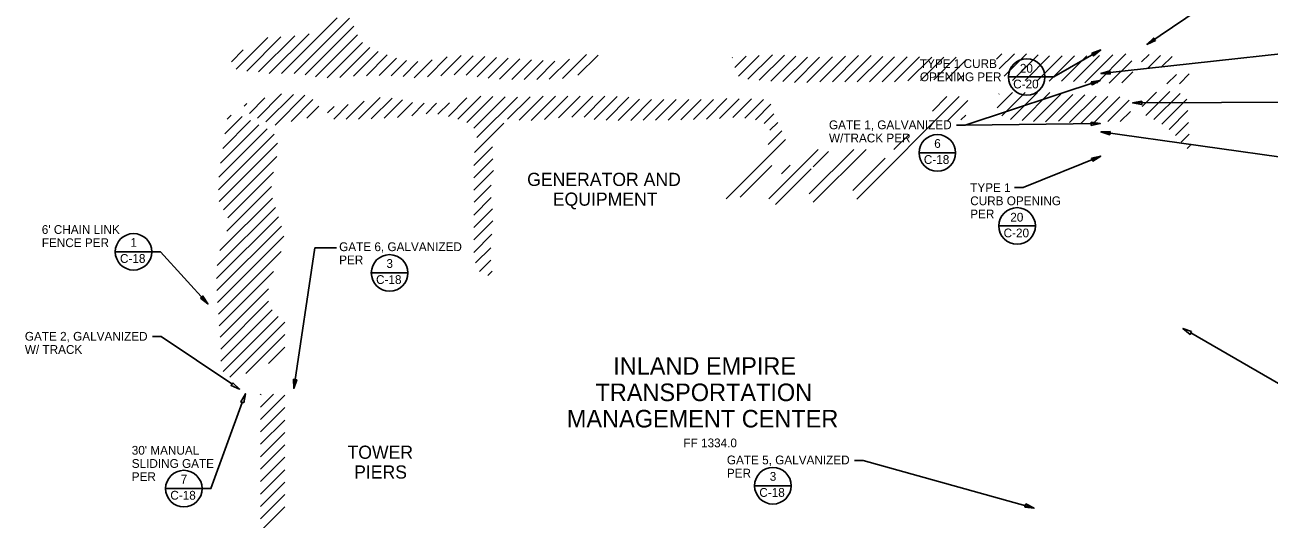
# Model space of a CAD drawing. Extents: x 0 to 3.5, y 0 to 2.5.
# Drawn here: x 0.832 to 2.248, y 0.842 to 1.404 of the extents above; entities that cross this region are included whole.
import ezdxf

# ---------------------------------------------------------------- set-up
doc = ezdxf.new("R2010")
doc.units = 0
for name, color, linetype in [('C-MARK', 7, 'Continuous'), ('C-TEXT', 7, 'Continuous'), ('C-TEXT-TITL', 7, 'Continuous'), ('G-TEXT', 7, 'Continuous'), ('Pavement Hatch', 7, 'Continuous')]:
    doc.layers.add(name, color=color, linetype=linetype)

msp = doc.modelspace()

# ---------------------------------------------------------------- linework, layer by layer
at = {"layer": 'C-MARK'}
for p, q in [((1.9515, 1.345), (1.9931, 1.345)), ((1.8498, 1.2586), (1.8914, 1.2586)), ((1.9406, 1.1754), (1.9822, 1.1754)), ((0.9347, 1.1459), (0.9764, 1.1459)), ((1.2262, 1.1219), (1.2678, 1.1219)), ((1.6625, 0.8795), (1.7042, 0.8795)), ((0.9919, 0.8763), (1.0336, 0.8763))]:
    msp.add_line(p, q, dxfattribs=at)
for points in [[(2.3985, 1.5709), (2.3885, 1.5709), (2.1092, 1.3821)], [(1.9931, 1.345), (2.0031, 1.345), (2.0566, 1.3758)], [(2.4063, 1.386), (2.3963, 1.386), (2.0568, 1.3491)], [(1.8922, 1.2901), (1.9022, 1.2901), (2.0561, 1.3411)], [(2.4072, 1.3169), (2.3972, 1.3169), (2.0929, 1.3154)], [(1.8922, 1.2901), (1.9022, 1.2901), (2.0561, 1.2919)], [(2.4072, 1.2349), (2.3972, 1.2349), (2.0568, 1.2825)], [(1.9583, 1.219), (1.9683, 1.219), (2.0566, 1.255)], [(1.1866, 1.1503), (1.162, 1.1503), (1.138, 0.9903)], [(0.9764, 1.1459), (0.9864, 1.1459), (1.0403, 1.0866)], [(0.9771, 1.0493), (0.9871, 1.0493), (1.0676, 0.9954)], [(2.3274, 0.9621), (2.3174, 0.9621), (2.1591, 1.0535)], [(1.0336, 0.8763), (1.0436, 0.8763), (1.0793, 0.9744)], [(1.7763, 0.9082), (1.7863, 0.9082), (1.9807, 0.854)]]:
    msp.add_lwpolyline(points, dxfattribs=at)
for centre in [(1.9723, 1.345), (1.8706, 1.2586), (1.9614, 1.1754), (0.9555, 1.1459), (1.247, 1.1219), (1.0128, 0.8763), (1.6833, 0.8795)]:
    msp.add_circle(centre, 0.0208, dxfattribs=at)
at = {"layer": 'C-TEXT'}
for points in [[(2.1189, 1.3864), (2.1092, 1.3821), (2.1168, 1.3894)], [(2.0466, 1.3722), (2.0566, 1.3758), (2.0484, 1.369)], [(2.0669, 1.352), (2.0568, 1.3491), (2.0673, 1.3484)], [(2.0456, 1.3396), (2.0561, 1.3411), (2.0468, 1.3361)], [(2.1033, 1.3173), (2.0929, 1.3154), (2.1033, 1.3136)], [(2.0456, 1.2936), (2.0561, 1.2919), (2.0457, 1.2899)], [(2.0674, 1.2829), (2.0568, 1.2825), (2.0668, 1.2793)], [(2.0462, 1.2527), (2.0566, 1.255), (2.0476, 1.2493)], [(1.0319, 1.0931), (1.0403, 1.0866), (1.0346, 1.0955)], [(2.16, 1.0551), (2.1501, 1.0587), (2.1582, 1.0519)], [(1.0687, 0.9969), (1.0763, 0.9896), (1.0666, 0.9938)], [(1.1378, 1.0009), (1.138, 0.9903), (1.1414, 1.0003)], [(1.081, 0.9738), (1.0829, 0.9842), (1.0776, 0.975)], [(1.9713, 0.8588), (1.9807, 0.854), (1.9702, 0.8553)]]:
    msp.add_lwpolyline(points, close=True, dxfattribs=at)
at = {"layer": 'Pavement Hatch'}
for p, q in [((1.1241, 1.3489), (1.1875, 1.4123)), ((1.1383, 1.3489), (1.2012, 1.4119)), ((1.151, 1.3475), (1.2062, 1.4027)), ((1.0725, 1.3538), (1.1084, 1.3898)), ((1.0845, 1.3517), (1.1234, 1.3906)), ((1.0979, 1.351), (1.139, 1.392)), ((1.11, 1.3489), (1.1554, 1.3943)), ((1.1628, 1.3452), (1.2106, 1.393)), ((1.0669, 1.3624), (1.0805, 1.376)), ((1.1758, 1.3441), (1.2162, 1.3844)), ((1.1903, 1.3444), (1.2244, 1.3784)), ((1.2058, 1.3458), (1.2341, 1.374)), ((1.2206, 1.3464), (1.2443, 1.3701)), ((1.235, 1.3466), (1.2548, 1.3665)), ((1.249, 1.3465), (1.2662, 1.3637)), ((1.2623, 1.3456), (1.2793, 1.3626)), ((1.275, 1.3442), (1.2953, 1.3646)), ((1.29, 1.3451), (1.3127, 1.3678)), ((1.3053, 1.3462), (1.3284, 1.3693)), ((1.3205, 1.3473), (1.3423, 1.3691)), ((1.3343, 1.347), (1.3556, 1.3683)), ((1.3466, 1.3451), (1.3688, 1.3673)), ((1.3591, 1.3435), (1.382, 1.3663)), ((1.3722, 1.3424), (1.3953, 1.3655)), ((1.3862, 1.3423), (1.4086, 1.3647)), ((1.4004, 1.3423), (1.4217, 1.3637)), ((1.4145, 1.3423), (1.4351, 1.3629)), ((1.4288, 1.3425), (1.4517, 1.3653)), ((1.4438, 1.3433), (1.4712, 1.3707)), ((1.4615, 1.3469), (1.4845, 1.3699)), ((1.6371, 1.3669), (1.6374, 1.3672)), ((1.64, 1.3557), (1.6531, 1.3688)), ((1.6444, 1.3459), (1.6679, 1.3694)), ((1.655, 1.3424), (1.683, 1.3704)), ((1.6679, 1.3412), (1.6965, 1.3698)), ((1.6811, 1.3403), (1.7096, 1.3687)), ((1.6948, 1.3398), (1.7227, 1.3677)), ((1.7078, 1.3386), (1.7366, 1.3674)), ((1.722, 1.3387), (1.7513, 1.368)), ((1.7367, 1.3393), (1.7662, 1.3688)), ((1.7511, 1.3395), (1.781, 1.3694)), ((1.7652, 1.3395), (1.7951, 1.3693)), ((1.7793, 1.3395), (1.8084, 1.3685)), ((1.7935, 1.3395), (1.8219, 1.3679)), ((1.8076, 1.3395), (1.8361, 1.3679)), ((1.8219, 1.3396), (1.8502, 1.3679)), ((1.8369, 1.3405), (1.8642, 1.3677)), ((1.8515, 1.3409), (1.878, 1.3674)), ((1.8666, 1.3419), (1.8921, 1.3674)), ((1.8805, 1.3416), (1.9037, 1.3648)), ((1.9379, 1.3653), (1.9441, 1.3714)), ((1.941, 1.3542), (1.9583, 1.3714)), ((1.9467, 1.3458), (1.9721, 1.3712)), ((1.9562, 1.3411), (1.9853, 1.3702)), ((1.9704, 1.3411), (1.9983, 1.3691)), ((1.9845, 1.3411), (2.0125, 1.3691)), ((1.9977, 1.3402), (2.0266, 1.3691)), ((2.0118, 1.3402), (2.0407, 1.3691)), ((2.0257, 1.3399), (2.0552, 1.3694)), ((2.0383, 1.3383), (2.0702, 1.3703)), ((2.052, 1.3379), (2.0853, 1.3712)), ((2.0661, 1.3379), (2.0918, 1.3635)), ((2.1031, 1.3621), (2.1116, 1.3706)), ((2.1098, 1.3546), (2.1247, 1.3695)), ((2.1263, 1.357), (2.1378, 1.3685)), ((1.8939, 1.3409), (1.9006, 1.3476)), ((2.0806, 1.3383), (2.0932, 1.3508)), ((2.132, 1.3372), (2.1427, 1.348)), ((2.1461, 1.3372), (2.1574, 1.3485)), ((1.0874, 1.3034), (1.1051, 1.3211)), ((1.0965, 1.2983), (1.1238, 1.3257)), ((1.1063, 1.294), (1.1375, 1.3252)), ((1.1166, 1.2902), (1.1507, 1.3243)), ((1.1348, 1.2942), (1.1598, 1.3193)), ((1.1976, 1.2971), (1.2182, 1.3176)), ((1.2118, 1.2971), (1.2364, 1.3217)), ((1.2261, 1.2972), (1.2498, 1.321)), ((1.2409, 1.298), (1.2619, 1.3189)), ((1.3139, 1.3002), (1.3349, 1.3212)), ((1.3248, 1.297), (1.3508, 1.323)), ((1.335, 1.293), (1.3647, 1.3227)), ((1.343, 1.2869), (1.3786, 1.3225)), ((1.3465, 1.2762), (1.3925, 1.3222)), ((1.3813, 1.2969), (1.407, 1.3225)), ((1.3944, 1.2958), (1.4217, 1.3231)), ((1.4082, 1.2955), (1.4358, 1.3231)), ((1.4235, 1.2967), (1.45, 1.3231)), ((1.4394, 1.2984), (1.4641, 1.3231)), ((1.4545, 1.2994), (1.4782, 1.3231)), ((1.4684, 1.2991), (1.4922, 1.323)), ((1.48, 1.2965), (1.506, 1.3226)), ((1.4934, 1.2958), (1.5194, 1.3219)), ((1.5073, 1.2956), (1.5316, 1.3199)), ((1.5215, 1.2956), (1.5452, 1.3193)), ((1.5356, 1.2957), (1.5593, 1.3193)), ((1.5499, 1.2958), (1.5734, 1.3193)), ((1.5642, 1.2959), (1.5876, 1.3193)), ((1.5786, 1.2962), (1.6017, 1.3193)), ((1.593, 1.2965), (1.6159, 1.3193)), ((1.6077, 1.297), (1.6311, 1.3204)), ((1.6224, 1.2976), (1.6451, 1.3203)), ((1.6377, 1.2987), (1.659, 1.32)), ((1.6513, 1.2982), (1.6725, 1.3194)), ((1.779, 1.206), (1.8956, 1.3226)), ((1.865, 1.3062), (1.8815, 1.3226)), ((1.8817, 1.2946), (1.9053, 1.3182)), ((1.9388, 1.3098), (1.9563, 1.3273)), ((1.9405, 1.3256), (1.9408, 1.326)), ((1.944, 1.3008), (1.9705, 1.3274)), ((1.9539, 1.2966), (1.9846, 1.3274)), ((1.9671, 1.2956), (1.9986, 1.3272)), ((1.9799, 1.2944), (2.0112, 1.3256)), ((1.9938, 1.2941), (2.0249, 1.3252)), ((2.0086, 1.2947), (2.0383, 1.3245)), ((2.021, 1.293), (2.0512, 1.3233)), ((2.0344, 1.2923), (2.0647, 1.3226)), ((2.0485, 1.2923), (2.0785, 1.3223)), ((2.0646, 1.2942), (2.0891, 1.3187)), ((2.1038, 1.3114), (2.1201, 1.3277)), ((2.1078, 1.3012), (2.1351, 1.3286)), ((2.1172, 1.2965), (2.147, 1.3263)), ((2.126, 1.2911), (2.1546, 1.3197)), ((1.0815, 1.3116), (1.0846, 1.3148)), ((1.1529, 1.2982), (1.1664, 1.3116)), ((1.1763, 1.304), (1.1838, 1.3115)), ((1.1835, 1.2971), (1.2, 1.3135)), ((1.2561, 1.299), (1.2732, 1.316)), ((1.2722, 1.3009), (1.2863, 1.3151)), ((1.2885, 1.3031), (1.3005, 1.3151)), ((1.3021, 1.3026), (1.3151, 1.3155)), ((1.6634, 1.2961), (1.6812, 1.314)), ((2.0788, 1.2942), (2.0903, 1.3057)), ((2.1343, 1.2853), (2.1558, 1.3068)), ((1.0544, 1.247), (1.098, 1.2906)), ((1.057, 1.2637), (1.0887, 1.2954)), ((1.0595, 1.2804), (1.0791, 1.2999)), ((1.0621, 1.2971), (1.0665, 1.3015)), ((1.3435, 1.259), (1.377, 1.2926)), ((1.6735, 1.2921), (1.6844, 1.303)), ((1.6798, 1.2843), (1.6889, 1.2933)), ((1.8974, 1.2961), (1.9029, 1.3016)), ((2.1416, 1.2785), (2.1564, 1.2932)), ((1.0522, 1.2165), (1.1156, 1.2799)), ((1.0526, 1.231), (1.1076, 1.2861)), ((1.6778, 1.2681), (1.6934, 1.2837)), ((1.8211, 1.2623), (1.8384, 1.2796)), ((2.1481, 1.2708), (2.1571, 1.2798)), ((1.0531, 1.2033), (1.1196, 1.2698)), ((1.3428, 1.2442), (1.3641, 1.2655)), ((1.6303, 1.2064), (1.6976, 1.2738)), ((1.6787, 1.2061), (1.735, 1.2625)), ((1.7247, 1.2118), (1.7754, 1.2625)), ((1.7293, 1.2023), (1.7895, 1.2624)), ((2.155, 1.2636), (2.1589, 1.2674)), ((1.0578, 1.1938), (1.1185, 1.2545)), ((1.3428, 1.2301), (1.3646, 1.2519)), ((1.7294, 1.2427), (1.7467, 1.26)), ((1.7745, 1.2156), (1.8113, 1.2524)), ((1.0627, 1.1846), (1.1147, 1.2366)), ((1.3428, 1.216), (1.3652, 1.2384)), ((1.646, 1.208), (1.6822, 1.2442)), ((1.6864, 1.1997), (1.7271, 1.2404)), ((1.6933, 1.2349), (1.7031, 1.2447)), ((1.0617, 1.1694), (1.1125, 1.2202)), ((1.3433, 1.2023), (1.3627, 1.2217)), ((1.0539, 1.1475), (1.1136, 1.2071)), ((1.3428, 1.1877), (1.3627, 1.2076)), ((1.0508, 1.1302), (1.1171, 1.1965)), ((1.3428, 1.1735), (1.3643, 1.195)), ((1.0501, 1.1154), (1.1206, 1.1859)), ((1.3428, 1.1594), (1.3646, 1.1812)), ((1.0505, 1.1017), (1.1241, 1.1752)), ((1.0512, 1.0882), (1.1266, 1.1636)), ((1.3429, 1.1453), (1.3636, 1.1661)), ((1.345, 1.1333), (1.3622, 1.1505)), ((1.0521, 1.075), (1.1235, 1.1464)), ((1.3493, 1.1234), (1.3622, 1.1364)), ((1.0531, 1.0618), (1.1149, 1.1236)), ((1.3589, 1.1189), (1.3639, 1.124)), ((1.054, 1.0486), (1.1093, 1.1039)), ((1.0548, 1.0352), (1.1093, 1.0897)), ((1.055, 1.0213), (1.1135, 1.0798)), ((1.0575, 1.0097), (1.1202, 1.0723)), ((1.0653, 1.0033), (1.1278, 1.0658)), ((1.0835, 1.0074), (1.1278, 1.0516)), ((1.1091, 1.0188), (1.1278, 1.0375)), ((1.1, 0.9832), (1.1005, 0.9837)), ((1.1, 0.9691), (1.1147, 0.9837)), ((1.1, 0.9549), (1.1278, 0.9827)), ((1.1, 0.9408), (1.1278, 0.9685)), ((1.1, 0.9267), (1.1278, 0.9544)), ((1.1, 0.9125), (1.1278, 0.9403)), ((1.1, 0.8984), (1.1278, 0.9261)), ((1.1, 0.8842), (1.1278, 0.912)), ((1.1, 0.8701), (1.1278, 0.8978)), ((1.1, 0.8559), (1.1278, 0.8837)), ((1.1, 0.8418), (1.1278, 0.8695)), ((1.1, 0.8277), (1.1278, 0.8554))]:
    msp.add_line(p, q, dxfattribs=at)

# ---------------------------------------------------------------- texts
at = {"layer": 'C-TEXT'}
for s, p in [('TYPE 1 CURB', (1.8507, 1.3552)), ('20', (1.9645, 1.3499)), ('OPENING PER', (1.8507, 1.3402)), ('C-20', (1.9569, 1.332)), ('GATE 1, GALVANIZED', (1.7472, 1.2855)), ('W/TRACK PER', (1.7472, 1.2705)), ('6', (1.867, 1.2643)), ('C-18', (1.8552, 1.246)), ('TYPE 1', (1.908, 1.214)), ('CURB OPENING', (1.908, 1.199)), ('PER', (1.908, 1.184)), ('20', (1.9536, 1.1803)), ("6' CHAIN LINK", (0.8511, 1.1663)), ('1', (0.952, 1.1516)), ('C-20', (1.946, 1.1624)), ('FENCE PER', (0.8511, 1.1513)), ('C-18', (0.9401, 1.1333)), ('3', (1.2434, 1.1276)), ('C-18', (1.2316, 1.1093)), ('GATE 2, GALVANIZED', (0.8318, 1.0447)), ('W/ TRACK', (0.8318, 1.0297)), ("30' MANUAL", (0.9535, 0.9149)), ('SLIDING GATE', (0.9535, 0.8999)), ('GATE 5, GALVANIZED', (1.631, 0.9039)), ('PER', (0.9535, 0.8849)), ('PER', (1.631, 0.8889)), ('3', (1.6798, 0.8852)), ('7', (1.0092, 0.882)), ('C-18', (0.9974, 0.8637)), ('C-18', (1.6679, 0.8669))]:
    msp.add_text(s, height=0.01, dxfattribs=at).set_placement(p)
for s, p in [('GATE 6, GALVANIZED', (1.1896, 1.1467)), ('PER', (1.1896, 1.1317))]:
    msp.add_text(s, height=0.01, rotation=360, dxfattribs=at).set_placement(p)
at = {"layer": 'C-TEXT-TITL'}
for s, height, p in [('GENERATOR AND', 0.015, (1.4036, 1.2209)), ('EQUIPMENT', 0.015, (1.4328, 1.1984)), ('INLAND EMPIRE', 0.02, (1.5016, 1.0059)), ('TRANSPORTATION', 0.02, (1.4814, 0.9759)), ('MANAGEMENT CENTER', 0.02, (1.4488, 0.9459)), ('TOWER', 0.015, (1.1991, 0.9102)), ('PIERS', 0.015, (1.2066, 0.8877))]:
    msp.add_text(s, height=height, dxfattribs=at).set_placement(p)
at = {"layer": 'G-TEXT'}
msp.add_text('FF 1334.0', height=0.01, dxfattribs=at).set_placement((1.5815, 0.9233))

doc.saveas('drawing.dxf')
